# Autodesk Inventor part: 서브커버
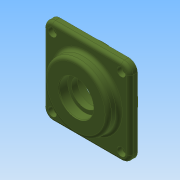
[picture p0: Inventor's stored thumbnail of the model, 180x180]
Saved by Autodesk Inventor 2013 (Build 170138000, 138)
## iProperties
Created: 2018-09
Part Number: 서브커버
Material: 알루미늄 6061
Document SubType Name: Modeling
Designer: mduedu
Density: 2.71 g/cm^3
Mass: 206.511 g
Surface Area: 197.007 cm^2
Volume: 76.2032 cm^3
Author: mduedu
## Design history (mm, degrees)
sketch "스케치1"
  geometry: L1 (-40, -40)-(40, -40); L2 (40, -40)-(40, 40); L3 (40, 40)-(-40, 40); L4 (-40, 40)-(-40, -40); L5 (-40, -40)-(40, 40); L6 (40, -40)-(-40, 40); 1 further point
  constraints: 12 end point, 2 midpoint, 2 parallel, 1 horizontal, 1 perpendicular
  dimensions: "d0" = 80 distance of L3.end L2.end; "d1" = 80 distance of L2.end L1.end
extrude "돌출1" new body sketch "스케치1" distance "d2" = 7; taper "d3" = 0 deg
sketch "스케치2"
  geometry: C1 r 30 at (0, 0); 1 further point
  constraints: 1 centre point, 1 coincident
  dimensions: "d4" = 60 diameter of C1
extrude "돌출2" join sketch "스케치2" distance "d5" = 10; taper "d6" = 0 deg
sketch "스케치3"
  geometry: C1 r 32.5 at (0, 0); 1 further point
  constraints: 1 centre point, 1 coincident
  dimensions: "d7" = 65 diameter of C1
extrude "돌출3" join sketch "스케치3" distance "d8" = 9; taper "d9" = 0 deg
sketch "스케치4"
  geometry: L1 (-32.5, -9)-(32.5, -9) reference; L2 (30, 17)-(-30, 17) reference; L3 (0, 17)-(0, -9); L4 (0, -9)-(20, -9); L5 (20, -9)-(20, 3); L6 (20, 3)-(0, 3); L7 (0, 3)-(0, -9); L8 (0, 3)-(12.5, 3); L9 (12.5, 3)-(12.5, 8.7); L10 (12.5, 8.7)-(0, 8.7); L11 (0, 8.7)-(0, 3); L12 (0, 8.7)-(16, 8.7); L13 (16, 8.7)-(16, 17); L14 (16, 17)-(0, 17); L15 (0, 17)-(0, 8.7); 1 further point
  constraints: 26 end point, 6 parallel, 3 horizontal, 3 perpendicular, 2 midpoint, 1 point on line
  dimensions: "d10" = 12 distance of L4.end L5.end; "d12" = 8.3 distance of L12.end L13.end; "d13" = 32 diameter of L13 L3; "d14" = 25 diameter of L9 L3; "d15" = 40 diameter of L5 L3
revolve "회전1" sketch "스케치4" stored, may be unused: angle "d16" = 90 deg
fillet "모깎기1" dims "d17" = 8
fillet "모깎기2" dims "d18" = 3
fillet "모깎기3" dims "d19" = 3
chamfer "모따기1" distance "d20" = 0.8; stored, may be unused: second distance "d21" = 2, angle "d22" = 30 deg
chamfer "모따기2" distance "d23" = 1; stored, may be unused: second distance "d24" = 2, angle "d25" = 30 deg
fillet "모깎기4" dims "d26" = 0.3
sketch "스케치5"
  geometry: A1 r 8 centre (-32, 32) between (-32, 40) and (-40, 32) reference; A2 r 8 centre (-32, -32) between (-40, -32) and (-32, -40) reference; A3 r 8 centre (32, -32) between (32, -40) and (40, -32) reference; A4 r 8 centre (32, 32) between (40, 32) and (32, 40) reference; 5 further points
  constraints: 4 coincident
hole "구멍1" sketch "스케치5" at (-32, 32), (32, 32), (32, -32), (-32, -32) diameter "d27" = 4.5; stored, may be unused: countersink angle "d31" = 90 deg, drill point angle "d33" = 118 deg; dims "d28" = 6, "d29" = 8, "d30" = 4.4, "d32" = 8
node "솔리드1"
